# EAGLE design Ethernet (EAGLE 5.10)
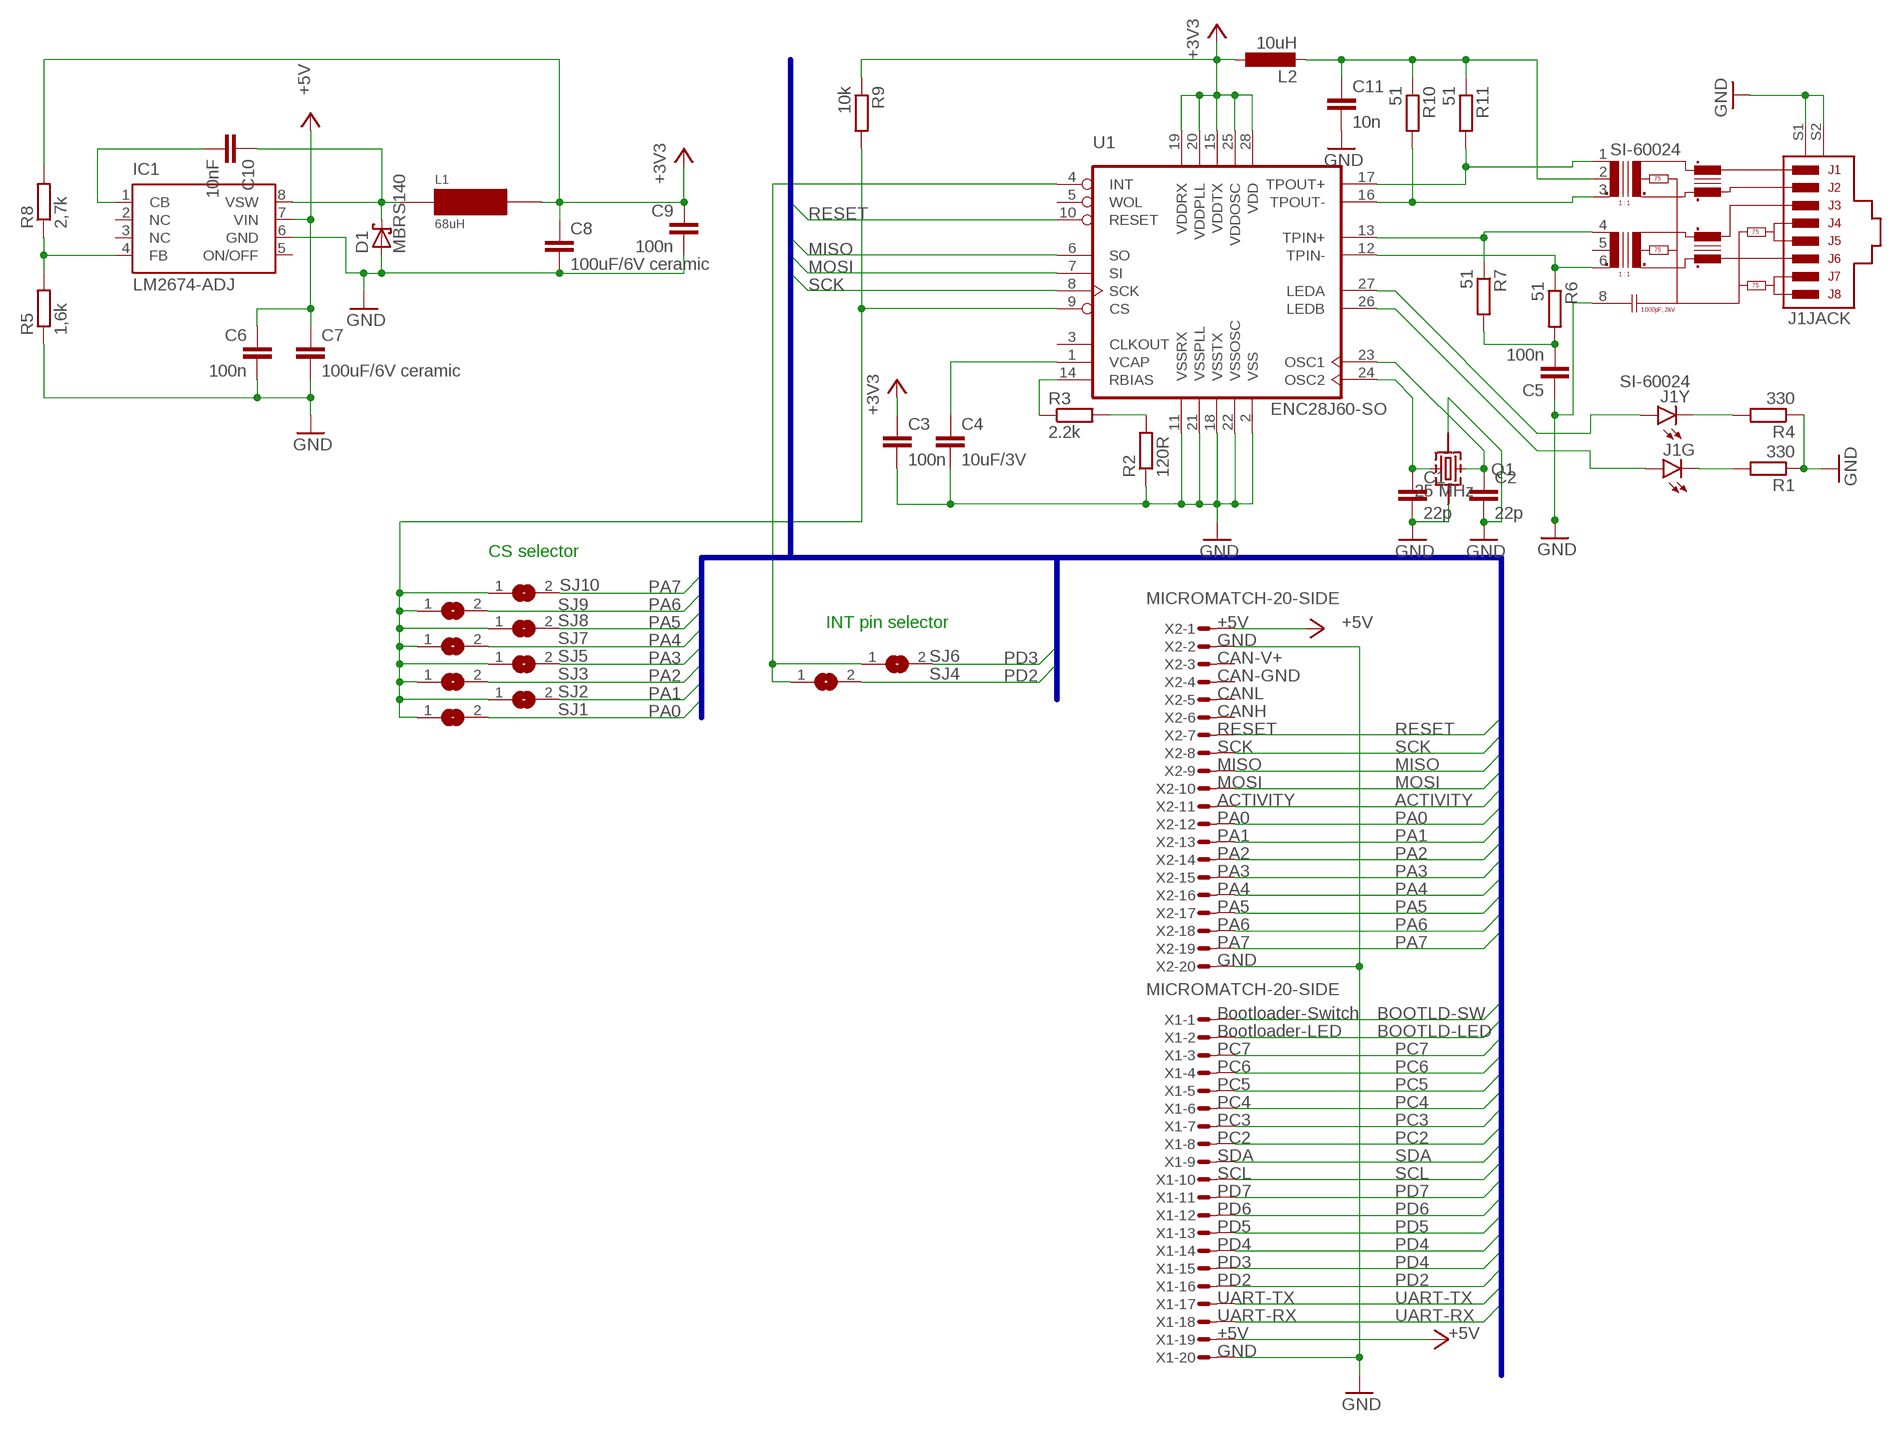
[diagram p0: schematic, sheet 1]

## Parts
C1  22p  C-EUC0805  [C0805]
C2  22p  C-EUC0805  [C0805]
C3  100n  C-EUC0805  [C0805]
C4  10uF/3V  C-EUC0805  [C0805]
C5  100n  C-EUC0805  [C0805]
C6  100n  C-EUC0805  [C0805]
C7  100uF/6V ceramic  C-EUC1206  [C1206]
C8  100uF/6V ceramic  C-EUC1206  [C1206]
C9  100n  C-EUC0805  [C0805]
C10  10nF  C-EUC0805  [C0805]
C11  10n  C-EUC0805  [C0805]
D1  MBRS140  MBRS130LT3  [SMB]
IC1  LM2674-ADJ  LM2674  [SO8]
J1  SI-60024  SI-40138  [SI-40138]
L1  68uH  SPULEN-PIS28XX  [L-PIS28XX]
L2  10uH  L-EUL5038P  [L5038P]
Q1  25 MHz  EUROQUARTZMQ  [EUROQUARTZ-MQ]
R1  330  R-EU_R0805  [R0805]
R2  120R  R-EU_R0805  [R0805]
R3  2.2k  R-EU_R0805  [R0805]
R4  330  R-EU_R0805  [R0805]
R5  1,6k  R-EU_R1206  [R1206]
R6  51  R-EU_R1206  [R1206]
R7  51  R-EU_R1206  [R1206]
R8  2,7k  R-EU_R1206  [R1206]
R9  10k  R-EU_R0805  [R0805]
R10  51  R-EU_R1206  [R1206]
R11  51  R-EU_R1206  [R1206]
SJ1  SJ  [SJ]
SJ2  SJ  [SJ]
SJ3  SJ  [SJ]
SJ4  SJ  [SJ]
SJ5  SJ  [SJ]
SJ6  SJ  [SJ]
SJ7  SJ  [SJ]
SJ8  SJ  [SJ]
SJ9  SJ  [SJ]
SJ10  SJ  [SJ]
U1  ENC28J60-SO  [SO28W]
X1  MICROMATCH-20-SIDE  [MICROMATCH-20-SIDE]
X2  MICROMATCH-20-SIDE  [MICROMATCH-20-SIDE]

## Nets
+3V3: C3.1 C8.1 C9.1 L1.2 L2.1 R8.2 R9.1 U1.15(VDDTX) U1.19(VDDRX) U1.20(VDDPLL) U1.25(VDDOSC) U1.28(VDD)
+5V: C6.1 C7.1 IC1.7(VIN) X1.19 X2.1
ACTIVITY: X2.11
BOOTLD-LED: X1.2
BOOTLD-SW: X1.1
GND: C1.2 C2.2 C3.2 C4.2 C5.1 C6.2 C7.2 C8.2 C9.2 C11.2 D1.A IC1.6(GND) J1.8(JACK:GND) J1.S1(JACK:S1) J1.S2(JACK:S2) Q1.2 Q1.4 R1.1 R2.1 R4.1 R5.1 U1.2(VSS) U1.11(VSSRX) U1.18(VSSTX) U1.21(VSSPLL) U1.22(VSSOSC) X1.20 X2.2 X2.20
MISO: U1.6(SO) X2.9
MOSI: U1.7(SI) X2.10
N$1: R2.2 R3.2
N$2: C10.1 D1.C IC1.8(VSW) L1.1
N$3: C4.1 U1.1(VCAP)
N$4: J1.GA(G:A) U1.26(LEDB)
N$5: J1.YA(Y:A) U1.27(LEDA)
N$6: J1.YC(Y:C) R4.2
N$7: C10.2 IC1.1(CB)
N$8: J1.GC(G:C) R1.2
N$9: J1.4(JACK:TD-) R7.1 U1.13(TPIN+)
N$10: C2.1 Q1.3 U1.23(OSC1)
N$11: J1.6(JACK:TD+) R6.1 U1.12(TPIN-)
N$12: C1.1 Q1.1 U1.24(OSC2)
N$13: C5.2 R6.2 R7.2
N$14: IC1.4(FB) R5.2 R8.1
N$15: C11.1 J1.2(JACK:CTR) L2.2 R10.1 R11.1
N$16: R3.1 U1.14(RBIAS)
N$17: J1.1(JACK:RD-) R11.2 U1.17(TPOUT+)
N$18: J1.3(JACK:RD+) R10.2 U1.16(TPOUT-)
N$20: SJ4.1 SJ6.1 U1.4(INT)
N$21: R9.2 SJ1.1 SJ2.1 SJ3.1 SJ5.1 SJ7.1 SJ8.1 SJ9.1 SJ10.1 U1.9(CS)
PA0: SJ1.2 X2.12
PA1: SJ2.2 X2.13
PA2: SJ3.2 X2.14
PA3: SJ5.2 X2.15
PA4: SJ7.2 X2.16
PA5: SJ8.2 X2.17
PA6: SJ9.2 X2.18
PA7: SJ10.2 X2.19
PC2: X1.8
PC3: X1.7
PC4: X1.6
PC5: X1.5
PC6: X1.4
PC7: X1.3
PD2: SJ4.2 X1.16
PD3: SJ6.2 X1.15
PD4: X1.14
PD5: X1.13
PD6: X1.12
PD7: X1.11
RESET: U1.10(RESET) X2.7
SCK: U1.8(SCK) X2.8
SCL: X1.10
SDA: X1.9
UART-RX: X1.18
UART-TX: X1.17
Unconnected: IC1.2(NC) IC1.3(NC) IC1.5(ON/OFF) J1.5(JACK:CTT) U1.3(CLKOUT) U1.5(WOL) X2.3 X2.4 X2.5 X2.6

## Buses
PA[0..7],PC[2..7],PD[2..7],SCK,MISO,MOSI,CAN-CS,BOOTLD-SW,CAN-INT,BOOTLD-LED,ACTIVITY,SDA,SCL,UART-RX,UART-TX,CLK,RESET

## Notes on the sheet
- CS selector
- INT pin selector | +5V
- GND
- CAN-V+
- CAN-GND
- CANL
- CANH
- RESET
- SCK
- MISO
- MOSI
- ACTIVITY
- PA0
- PA1
- PA2
- PA3
- PA4
- PA5
- PA6
- PA7
- GND
- Bootloader-Switch
- Bootloader-LED
- PC7
- PC6
- PC5
- PC4
- PC3
- PC2
- SDA
- SCL
- PD7
- PD6
- PD5
- PD4
- PD3
- PD2
- UART-TX
- UART-RX
- +5V
- GND

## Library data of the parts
C1-C11 = rcl:C-EU: CAPACITOR, European symbol
D1 = diode:MBRS130LT3: Schottky Power Rectifier
IC1 = lm2674-auml.se:LM2674
J1 = 11my-mechanics:SI-40138: MagJack SI-60024 SI-40138 SI-40139 SI-40140
L1 = 11my-RCA:SPULEN: SMD-Power-Induktivitten
L2 = rcl:L-EU: INDUCTOR, European symbol
Q1 = 11my-crystals:EUROQUARTZ: Euroquartz-Quarze, via Reichelt Variante MT hat umgekehrte Anschlüsse
R1-R11 = rcl:R-EU_: RESISTOR, European symbol
SJ1-SJ10 = jumper:SJ: SMD solder JUMPER
U1 = enc28j60:ENC28J60-*: Microchip 10Mbit Ethernet controller with SPI interface Improved SOIC28 layout (pads in 0.01 raster, pin1 slightly smaller). Pin 6 (SO) changed from Out (paralleling several Outs gives an error) to OC. Author: Profi from mikrocontroller.net - forum Date: 2006.0827
X1 X2 = apbteam_con-amp-micromatch:MICROMATCH-20: Micro-MaTch 20 Straight connector: Suited for both, female and male.

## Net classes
0 default: width 0.15 mm
1 Power: width 0.5 mm

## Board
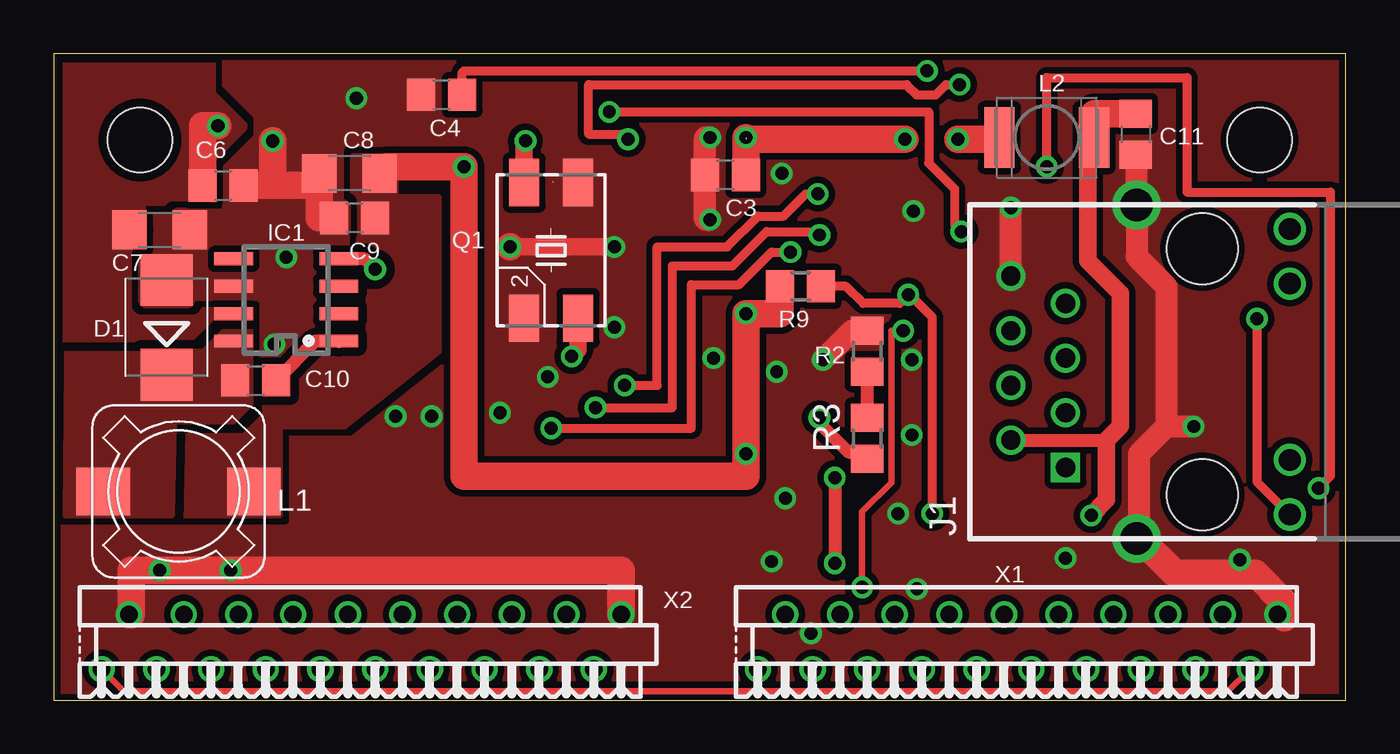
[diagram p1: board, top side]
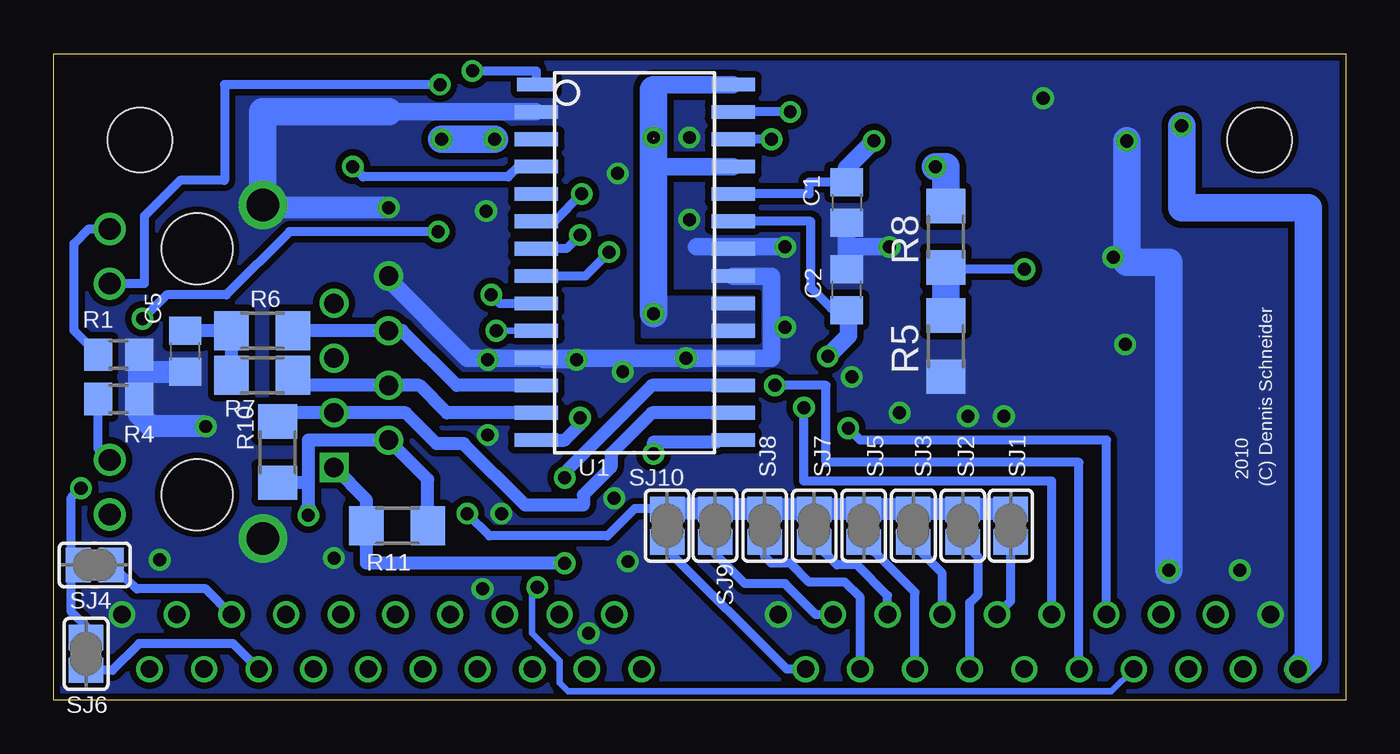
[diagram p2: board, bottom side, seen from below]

Size 60 x 30 mm. Coordinates in mm from the lower left corner, seen from the top.
Outline: 0,0 60,0 60,30 0,30 0,0
Copper layers (1+2*15+16): Top 0.035mm / dielectric 0.36mm / layer 2 0.018mm / dielectric 0.71mm / layer 15 0.018mm / dielectric 0.36mm / Bottom 0.035mm
Design rules "q-print.info *": minimum track width 6mil, minimum drill 0.3mm, track to track 6mil, track to pad 6mil, pad to pad 6mil, via to via 6mil, smd to smd 6mil, copper to edge 8mil, drill to drill 10mil, minimum pad ring 8mil, minimum via ring 8mil, stop-mask expansion 4mil, vias tented up to drill 16mil, thermal gap 10mil
Holes 3 mm at 4,26 56,26

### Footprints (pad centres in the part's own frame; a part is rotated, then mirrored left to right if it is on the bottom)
C0805 = smd 1.3 x 1.5: 1 -0.95,0; 2 0.95,0
C1206 = smd 1.6 x 1.8: 1 -1.4,0; 2 1.4,0
SMB = smd 2.4 x 2.4: A 2.2,0; C -2.2,0
SO8 = smd 0.6 x 1.8: 1 -1.905,-2.44; 2 -0.635,-2.44; 3 0.635,-2.44; 4 1.905,-2.44; 5 1.905,2.44; 6 0.635,2.44; 7 -0.635,2.44; 8 -1.905,2.44
SI-40138 = drill 0.9 square: 1 -4.445,6.35 | drill 0.9 round: 2 -3.175,8.89; 3 -1.905,6.35; 4 -0.635,8.89; 5 0.635,6.35; 6 1.905,8.89; 7 3.175,6.35; 8 4.445,8.89 | drill 1 round: GA 4.089,-4.064; GC 6.629,-4.064; YA -6.629,-4.064; YC -4.089,-4.064 | drill 1.5 round: S1 -7.747,3.048; S2 7.747,3.048 | hole 3.3: -5.715,0; 5.715,0
L-PIS28XX = smd 2.2 x 2.5: 1 0,3.5; 2 0,-3.5
L5038P = smd 1.4 x 2.8: 1 -2.2,0; 2 2.2,0
EUROQUARTZ-MQ = smd 2.2 x 1.4: 1 -3.15,-1.25; 2 3.15,-1.25; 3 3.15,1.25; 4 -3.15,1.25
R0805 = smd 1.3 x 1.5: 1 -0.95,0; 2 0.95,0
R1206 = smd 1.6 x 1.803: 1 -1.422,0; 2 1.422,0
SJ = smd 1.168 x 1.6: 1 -0.762,0; 2 0.762,0
SO28W = smd 0.635 x 1.778: 1 -8.255,-4.572 | smd 0.635 x 2.032: 2 -6.985,-4.572; 3 -5.715,-4.572; 4 -4.445,-4.572; 5 -3.175,-4.572; 6 -1.905,-4.572; 7 -0.635,-4.572; 8 0.635,-4.572; 9 1.905,-4.572; 10 3.175,-4.572; 11 4.445,-4.572; 12 5.715,-4.572; 13 6.985,-4.572; 14 8.255,-4.572; 15 8.255,4.572; 16 6.985,4.572; 17 5.715,4.572; 18 4.445,4.572; 19 3.175,4.572; 20 1.905,4.572; 21 0.635,4.572; 22 -0.635,4.572; 23 -1.905,4.572; 24 -3.175,4.572; 25 -4.445,4.572; 26 -5.715,4.572; 27 -6.985,4.572; 28 -8.255,4.572
MICROMATCH-20-SIDE = drill 0.813 round: 1 12.065,1.27; 2 10.795,-1.27; 3 9.525,1.27; 4 8.255,-1.27; 5 6.985,1.27; 6 5.715,-1.27; 7 4.445,1.27; 8 3.175,-1.27; 9 1.905,1.27; 10 0.635,-1.27; 11 -0.635,1.27; 12 -1.905,-1.27; 13 -3.175,1.27; 14 -4.445,-1.27; 15 -5.715,1.27; 16 -6.985,-1.27; 17 -8.255,1.27; 18 -9.525,-1.27; 19 -10.795,1.27; 20 -12.065,-1.27

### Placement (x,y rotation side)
C1  23.18,23.1 270 bottom
C2  23.18,19.05 90 bottom
C3  31.19,24.37 180 top
C4  18.02,28.1 180 top
C5  53.9,16.19 90 bottom
C6  7.86,23.89 0 top
C7  4.92,21.83 0 top
C8  13.73,24.45 180 top
C9  13.97,22.38 180 top
C10  9.37,14.84 0 top
C11  50.24,26.27 270 top
D1  5.24,17.3 90 top
IC1  10.79,18.57 90 top
J1  53.34,15.24 90 top
L1  5.79,9.68 90 top
L2  46.12,26.11 0 top
Q1  23.1,20.88 270 top
R1  56.99,16.03 180 bottom
R2  37.78,16.19 270 top
R3  37.78,12.14 90 top
R4  56.99,13.97 180 bottom
R5  18.57,16.43 90 bottom
R6  50.32,17.15 180 bottom
R7  50.32,15.08 180 bottom
R8  18.57,21.51 90 bottom
R9  34.69,19.21 0 top
R10  49.61,11.51 90 bottom
R11  44.05,8.1 180 bottom
SJ1  15.56,8.1 270 bottom
SJ2  17.78,8.1 270 bottom
SJ3  20.08,8.1 270 bottom
SJ4  58.1,6.27 0 bottom
SJ5  22.38,8.1 270 bottom
SJ6  58.5,2.14 270 bottom
SJ7  24.69,8.1 270 bottom
SJ8  26.99,8.1 270 bottom
SJ9  29.29,8.1 270 bottom
SJ10  31.51,8.1 270 bottom
U1  33.02,20.32 270 bottom
X1  44.77,2.7 180 top
X2  14.29,2.7 180 top

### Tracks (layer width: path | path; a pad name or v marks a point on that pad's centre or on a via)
+3V3  (via drill 0.6, 0.61)  (1 unrouted)
  Top 1.27: R9.1 33.74,17.94 v32.15,17.94 v32.15,11.43 32.15,10.4 19.06,10.4 19.06,22.54 19.05,22.54 v19.05,24.77 15.45,24.77 C8.1 | 32.14,26.04 v39.53,26.04 | v41.99,26.04 43.84,26.04 L2.1 | v32.15,26.11 C3.1
  Bottom 0.61: U1.15 29.13,12.06 29.21,11.99 32.15,11.99 v32.15,11.43
  Bottom 0.813: 32.15,24.77 U1.25 | U1.28 32.15,28.57 32.15,27.94
  Bottom 1.27: 32.15,18.41 v32.15,17.94 32.15,24.77 v32.15,26.11 32.15,27.94 32.15,28.34 | v39.53,26.04 v41.99,26.04 | v19.05,24.77 18.57,24.77 R8.2
  pour Top (isolate 0.406, rank 3, no thermals): 4.13,8.57 10.48,8.57 10.48,12.7 13.49,12.7 17.86,16.19 17.86,23.34 15.88,23.34 15.88,25.24 13.89,25.24 13.89,21.43 13.41,20.95 12.46,20.95 12.46,16.27 12.3,15.64 10.8,15.48 10.79,14.29 4.21,14.29
  pour Bottom (rank 3, no thermals): 27.54,16.91 32.62,16.91 32.62,18.49 32.62,18.65 27.86,18.65 27.54,18.65
+5V  (via drill 0.61)
  Top 0.305: X2.1 3.25,0.4 54.53,0.4 X1.19
  Top 0.406: X2.1
  Top 1.016: C7.1 3.81,21.83
  Top 1.27: v7.62,26.67 6.91,26.67 C6.1
  Bottom 1.27: v7.62,26.67 7.62,22.86 1.75,22.86 1.75,1.91 X2.1
  pour Top (isolate 0.406, no thermals): 7.38,30 7.38,28.18 8.89,26.67 8.89,26.59 7.38,25.08 7.38,23.1 4.13,23.1 4.13,21.03 3.57,21.03 3.57,18.1 9.13,18.1 9.13,17.78 7.38,17.78 6.35,16.75 0,16.75 0,30.08
GND  (via drill 0.6, 0.61)
  Top 0.813: v21.19,21.03 v26.04,21.03 | 50.4,7.6 50.4,7.54
  Top 1.016: 51.67,12.7 v52.94,12.7 | 51.67,12.7 50.4,11.43 50.4,7.6 J1.S1 | 51.67,12.7 51.67,19.21 50.29,20.59 J1.S2 50.29,25.28 C11.2 | J1.8 v44.45,22.86 | v35.72,15.8 37.07,17.14 R2.1 | v30.48,22.3 30.24,22.3 C3.2 30.24,26.11 v30.48,26.11
  Top 1.27: X2.2 3.59,3.97 3.59,6.03 v8.21,6.03 26.35,6.03 X2.20 | 10.16,23.89 C6.2 | v10.16,25.96 10.16,23.89 | C9.2 12.33,22.38 C8.2 12.33,23.89 10.16,23.89 | 50.4,7.54 52.07,5.87 55.8,5.87 57.15,4.52 57.15,3.81 | v21.19,21.03
  Bottom 0.813: C2.2 23.18,21.03 | C2.2 | 23.18,21.03 C1.2 | 23.18,21.03 v21.19,21.03 | 28.45,21.03 v26.04,21.03 30.16,21.03 | J1.8 44.45,19.53 40.8,15.88 U1.11 37.23,15.88 | 44.45,27.3 U1.2 | U1.21 26.67,19.68 26.67,15.88 U1.18 37.23,15.88 | v35.72,15.8 37.23,15.8 37.23,15.88
  Bottom 1.016: v52.94,12.7 55.49,12.7 56.04,13.26 R4.1 56.04,15.24 | v44.45,22.86 50.16,22.86 J1.S2 | 56.04,15.24 R1.1 | C5.1 56.04,15.24
  Bottom 1.27: 44.45,27.3 50.29,27.3 J1.S2 | v8.21,6.03 8.21,20.32 10.16,20.32 v10.16,25.96
  other vias: 33.97,9.37 39.85,12.3 33.81,24.45 39.93,22.7 33.34,6.43 46.99,6.59 55.09,6.51 39.85,15.8 40.08,5.16 35.16,3.1 39.21,8.65 30.64,15.88 20.72,13.34 15.88,13.18 10.24,16.51 4.92,6.03 22.94,15 26.04,17.3 33.58,15.24 14.05,27.94 10.79,20.56 17.54,13.18
  pour Bottom (isolate 0.3, rank 5, no thermals): 0,0 60,0 60,30 0,30
  pour Top (isolate 0.3, rank 4, no thermals): 0,0 0,30 60,30 60,0
  pour Top (isolate 0.406, rank 5, no thermals): 0,5.08 19.05,5.08 19.05,21.59 17.78,21.59 17.78,29.92 0,30
MISO  (via drill 0.6)
  Top 0.406: v35.48,23.5 34.92,23.5 33.89,22.46 32.7,22.46 31.27,21.03 28.02,21.03 28.02,14.61 v26.51,14.61
  Bottom 0.406: U1.6 36.75,22.23 v35.48,23.5 | v26.51,14.61 24.13,14.61 24.13,11.03 12.38,11.03 X2.9
MOSI  (via drill 0.6)
  Top 0.406: v25.16,13.57 28.73,13.57 28.73,20.16 31.51,20.16 33.1,21.75 35.56,21.75 v35.56,21.59
  Bottom 0.406: U1.7 36.2,20.95 v35.56,21.59 | X2.10 13.65,10.16 25.16,10.16 v25.16,13.57
N$1
  Top 0.61: R2.2 R3.2
N$2
  pour Top (isolate 0.406, rank 2, no thermals): 9.13,17.78 9.13,13.73 8.33,12.94 5.56,12.94 5.48,8.57 0.56,8.57 0.64,17.78
N$3  (via drill 0.6)
  Top 0.406: v40.56,29.21 19.05,29.21 18.97,29.13 C4.1
  Bottom 0.406: v40.56,29.21 37.59,29.21 U1.1
N$4  (via drill 0.6)
  Top 0.406: v26.67,26.04 26.43,26.27 24.84,26.27 24.84,28.57 39.61,28.57 40.08,28.1 40.96,28.1 41.43,28.57 v42.07,28.57
  Bottom 0.406: v26.67,26.04 U1.26 | v42.07,28.57 52.07,28.57 52.07,24.13 54.13,24.13 55.8,22.46 55.8,19.33 J1.GA
N$5  (via drill 0.6)
  Top 0.406: v25.8,27.3 40.64,27.3 40.64,24.92 41.83,23.73 41.83,22.07 v42.15,21.75 | v55.88,17.7 55.88,10.13 J1.YA
  Bottom 0.406: v25.8,27.3 U1.27 | v42.15,21.75 49.05,21.75 51.99,18.81 54.77,18.81 v55.88,17.7
N$6
  Bottom 0.406: R4.2 57.94,11.69 J1.YC
N$7
  Top 0.61: 13.23,16.65 IC1.1 12.14,16.67 C10.2
N$8
  Bottom 0.406: J1.GC 58.38,21.87 59.05,21.19 59.05,17.15 R1.2
N$9
  Bottom 0.61: U1.13 41.75,13.34 43.02,14.61 J1.4 48.42,14.61 R7.1
N$10  (via drill 0.6)
  Top 0.813: Q1.3 24.35,16.25 v24.05,15.95
  Bottom 0.406: U1.23 24.84,22.23 24.84,19.13 23.89,18.18 23.25,18.18 C2.1
  Bottom 0.813: C2.1 23.1,18.1 23.1,16.91 v24.05,15.95
N$11
  Bottom 0.61: R6.1 49.37,17.14 J1.6 43.81,17.14 41.27,14.61 U1.12
N$12  (via drill 0.6)  (1 unrouted)
  Top 0.813: Q1.1 21.85,25.9 v21.91,25.96
  Bottom 0.406: U1.24 24.92,23.5 24.92,24.05 C1.1
  Bottom 0.813: C1.1 23.18,24.69 v21.91,25.96
N$13
  Bottom 0.61: C5.2 53.34,17.14 R6.2 51.75,14.61 R7.2
N$14  (via drill 0.61)
  Top 0.61: v14.92,20 14.45,20.48 IC1.4
  Bottom 0.406: v14.92,20 18.57,20 R8.1
  Bottom 1.27: R8.1 R5.2
N$15  (via drill 0.6)
  Top 0.61: J1.2 48.9,12.06
  Top 0.813: v48.18,8.57 48.9,9.29 48.9,12.06 49.53,12.7 49.53,18.89 48.02,20.4 48.02,26.11 L2.2
  Top 1.27: L2.2 48.32,27.22 C11.1
  Bottom 0.61: 48.18,10.09 48.18,12.06 J1.2 42.63,10.25 R11.1 | 48.18,10.09 R10.1 | 48.18,10.09 v48.18,8.57
  Bottom 0.813: v48.18,8.57 48.18,8.81
N$16  (via drill 0.61)
  Top 0.61: 37.7,11.27 R3.1 37.47,11.51 36.91,11.51 35.56,12.86 v35.56,13.1
  Bottom 0.61: v35.56,13.1 35.56,12.78 36.27,12.06 U1.14
N$17  (via drill 0.6)
  Top 0.61: v36.27,10.32 v36.27,6.35
  Bottom 0.61: U1.17 32.23,14.61 36.27,10.56 v36.27,10.32 | v36.27,6.35 45.48,6.35 R11.2 45.48,9.28 J1.1
N$18
  Bottom 0.61: R10.2 49.61,12.62 49.61,13.34 J1.3 43.66,13.34 42.23,11.91 40.96,11.91 38.1,9.05 35.4,9.05 35.4,9.53 34.13,10.79 34.13,11.43 32.23,13.34 U1.16
N$20  (via drill 0.6, 0.61)
  Top 0.406: v46.12,24.77 46.12,28.89 52.63,28.89 52.63,23.57 59.29,23.57 59.29,10.4 v58.74,9.84
  Bottom 0.406: U1.4 38.42,24.77 38.89,24.29 45.64,24.29 v46.12,24.77 | v58.74,9.84 59.21,9.36 59.21,6.62 SJ4.1 59.21,5.92 59.21,4.13 58.5,3.41 SJ6.1
N$21  (via drill 0.6)
  Top 0.406: R9.2 36.8,19.21 U1.9 39.29,18.41 v39.69,18.81 39.77,18.81 40.8,17.78 v40.8,8.65
  Bottom 0.406: v39.69,18.81 39.29,18.41 U1.9 | v40.8,8.65 39.77,7.62 34.29,7.62 33.02,8.89 31.51,8.89 SJ10.1
  Bottom 0.61: SJ9.1 29.29,9.02 | SJ9.1 | SJ5.1 | SJ7.1
  Bottom 1.016: 31.51,8.89 29.29,8.89 SJ9.1 SJ8.1 SJ7.1 SJ5.1 | SJ5.1 | SJ3.1 SJ5.1 | SJ3.1 | SJ3.1 SJ2.1 SJ1.1
PA0
  Bottom 0.406: SJ1.2 15.56,4.6 X2.12
PA1
  Bottom 0.406: X2.13 17.46,4.52 17.07,4.92 17.07,6.62 SJ2.2
PA2
  Bottom 0.406: SJ3.2 20.08,7.22 18.73,5.87 X2.14
PA3
  Bottom 0.406: X2.15 20,5 21.91,6.91 21.95,6.91 SJ5.2
PA4
  Bottom 0.406: X2.16 21.27,4.84 22.7,6.27 23.62,6.27 SJ7.2
PA5
  Bottom 0.406: X2.17 22.54,4.76 23.26,5.48 24.92,5.48 25.8,6.35 26.67,6.35 26.99,6.67 SJ8.2
PA6
  Bottom 0.406: X2.18 24.61,3.97 26.04,5.4 27.91,5.4 29.29,6.78 SJ9.2
PA7
  Bottom 0.406: X2.19 25.96,1.43 31.51,6.99 SJ10.2
PD2
  Bottom 0.406: SJ4.2 56.15,5.16 52.94,5.16 X1.16
PD3
  Bottom 0.406: SJ6.2 57.28,1.38 56.04,2.62 51.67,2.62 X1.15
RESET  (via drill 0.61)
  Top 0.305: v37.54,5.24 37.54,8.73 38.89,10.08 38.89,17.14 v39.45,17.14
  Bottom 0.305: X2.7 10.87,0.4 36.12,0.4 36.51,0.79 36.51,1.83 37.78,3.1 37.78,5 v37.54,5.24 | v39.45,17.14 U1.10
SCK  (via drill 0.6)
  Top 0.406: v34.21,20.8 33.34,20.8 32.38,19.84 | 32.38,19.84 | 32.38,19.84 31.83,19.29 29.61,19.29 29.61,12.62 v23.1,12.62
  Bottom 0.406: U1.8 35.32,19.68 v34.21,20.8 | X2.8 11.11,12.06 22.54,12.06 v23.1,12.62

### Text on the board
bPlace: (C) Dennis Schneider | 2010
